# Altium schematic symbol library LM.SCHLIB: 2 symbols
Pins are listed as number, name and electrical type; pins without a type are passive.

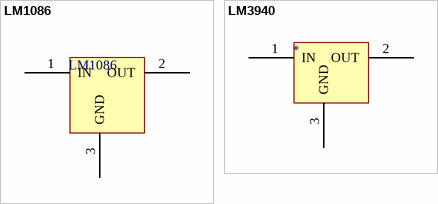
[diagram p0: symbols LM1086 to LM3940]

## LM1086
designator LM1086
pins: 1 IN, 2 OUT, 3 GND

## LM3940
designator *
pins: 1 IN, 2 OUT, 3 GND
